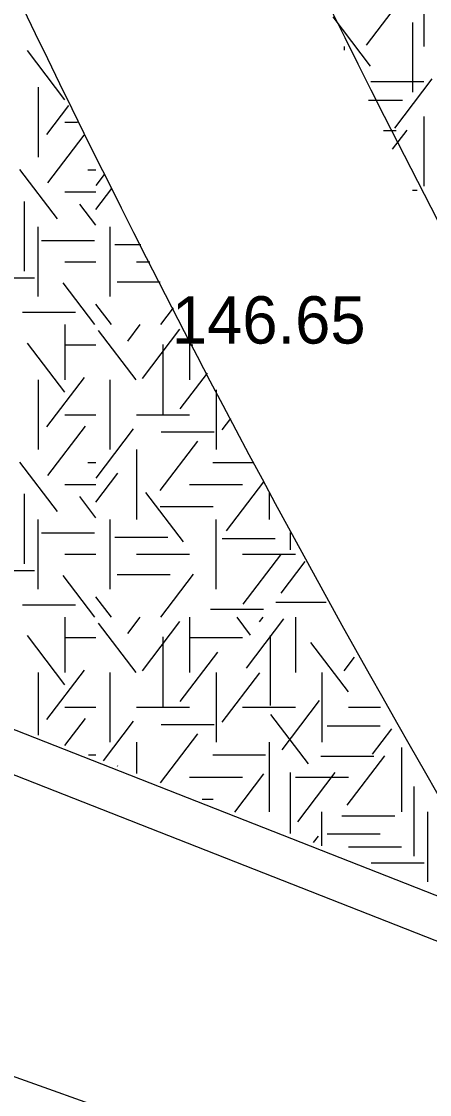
# Model space of a CAD drawing. Extents: x 419677 to 421689, y 4450851 to 4452923.
# Drawn here: x 420247.89 to 420258.24, y 4452050.44 to 4452077.62 of the extents above; entities that cross this region are included whole.
import ezdxf

# ---------------------------------------------------------------- set-up
doc = ezdxf.new("R2010")
doc.units = 0
for name, color, linetype in [('AA_HH', 7, 'Continuous'), ('Level 41', 7, 'Continuous'), ('Level 62', 7, 'Continuous')]:
    doc.layers.add(name, color=color, linetype=linetype)

msp = doc.modelspace()

# ---------------------------------------------------------------- linework, layer by layer
at = {"layer": 'Level 41'}
for p, q in [((420256.636, 4452077.019), (420257.585, 4452078.269)), ((420258.089, 4452078.382), (420258.089, 4452076.984)), ((420256.743, 4452076.493), (420255.794, 4452077.742)), ((420257.807, 4452077.594), (420257.807, 4452075.827)), ((420248.989, 4452075.638), (420248.04, 4452076.887)), ((420256.075, 4452076.984), (420256.075, 4452076.899)), ((420256.746, 4452076.1), (420258.089, 4452076.1)), ((420257.356, 4452074.916), (420258.305, 4452076.166)), ((420248.317, 4452075.954), (420248.317, 4452074.187)), ((420248.317, 4452075.954), (420248.317, 4452074.187)), ((420248.537, 4452074.761), (420249.091, 4452075.491)), ((420256.693, 4452075.63), (420257.549, 4452075.63)), ((420258.089, 4452075.217), (420258.089, 4452073.45)), ((420248.988, 4452075.07), (420249.309, 4452075.07)), ((420248.563, 4452073.535), (420249.48, 4452074.741)), ((420257.068, 4452074.86), (420257.389, 4452074.86)), ((420257.299, 4452074.386), (420257.666, 4452074.869)), ((420248.802, 4452072.623), (420247.853, 4452073.872)), ((420249.572, 4452073.863), (420249.776, 4452073.863)), ((420249.786, 4452073.466), (420249.997, 4452073.744)), ((420248.988, 4452073.303), (420249.776, 4452073.303)), ((420249.776, 4452072.857), (420250.181, 4452073.39)), ((420257.803, 4452073.352), (420257.923, 4452073.352)), ((420247.963, 4452073.065), (420247.963, 4452071.297)), ((420249.776, 4452072.463), (420249.37, 4452072.997)), ((420248.317, 4452070.652), (420248.317, 4452072.42)), ((420250.138, 4452070.652), (420250.138, 4452072.42)), ((420248.399, 4452072.077), (420249.742, 4452072.077)), ((420250.261, 4452071.971), (420250.917, 4452071.971)), ((420248.988, 4452071.536), (420249.776, 4452071.536)), ((420250.809, 4452071.536), (420251.142, 4452071.536)), ((420246.881, 4452071.129), (420248.224, 4452071.129)), ((420249.747, 4452069.943), (420248.945, 4452070.999)), ((420250.315, 4452071.025), (420251.407, 4452071.025)), ((420250.17, 4452069.943), (420249.776, 4452070.461)), ((420251.423, 4452069.943), (420251.747, 4452070.37)), ((420247.92, 4452070.255), (420249.263, 4452070.255)), ((420248.988, 4452069.943), (420248.988, 4452068.545)), ((420248.988, 4452069.943), (420248.988, 4452068.545)), ((420250.797, 4452068.545), (420249.848, 4452069.795)), ((420250.586, 4452069.526), (420250.903, 4452069.943)), ((420250.957, 4452068.58), (420251.906, 4452069.83)), ((420252.152, 4452069.589), (420252.152, 4452068.545)), ((420248.989, 4452068.229), (420248.04, 4452069.478)), ((420248.988, 4452069.429), (420249.776, 4452069.429)), ((420251.477, 4452069.441), (420251.477, 4452067.674)), ((420252.152, 4452069.429), (420252.235, 4452069.429)), ((420251.917, 4452067.808), (420252.606, 4452068.715)), ((420248.317, 4452068.545), (420248.317, 4452066.778)), ((420248.317, 4452068.545), (420248.317, 4452066.778)), ((420248.537, 4452067.352), (420249.486, 4452068.602)), ((420250.138, 4452066.778), (420250.138, 4452068.545)), ((420252.824, 4452068.294), (420252.824, 4452066.778)), ((420248.988, 4452067.661), (420249.776, 4452067.661)), ((420250.809, 4452067.661), (420252.152, 4452067.661)), ((420248.563, 4452066.126), (420249.513, 4452067.375)), ((420252.983, 4452067.283), (420253.2, 4452067.569)), ((420249.786, 4452066.057), (420250.735, 4452067.306)), ((420251.433, 4452067.227), (420252.776, 4452067.227)), ((420250.809, 4452066.778), (420250.809, 4452065.011)), ((420251.411, 4452065.74), (420252.36, 4452066.99)), ((420248.802, 4452065.214), (420247.853, 4452066.463)), ((420249.572, 4452066.454), (420249.776, 4452066.454)), ((420252.739, 4452066.454), (420253.778, 4452066.454)), ((420249.776, 4452065.448), (420250.335, 4452066.184)), ((420253.088, 4452064.724), (420254.032, 4452065.966)), ((420248.988, 4452065.894), (420249.776, 4452065.894)), ((420251.996, 4452064.443), (420251.047, 4452065.693)), ((420252.152, 4452065.894), (420253.495, 4452065.894)), ((420254.167, 4452065.705), (420254.167, 4452065.011)), ((420247.963, 4452065.656), (420247.963, 4452063.888)), ((420249.776, 4452065.054), (420249.37, 4452065.588)), ((420251.406, 4452065.334), (420252.749, 4452065.334)), ((420248.317, 4452063.243), (420248.317, 4452065.011)), ((420250.138, 4452063.243), (420250.138, 4452065.011)), ((420252.824, 4452063.243), (420252.824, 4452065.011)), ((420248.399, 4452064.668), (420249.742, 4452064.668)), ((420254.699, 4452064.679), (420254.699, 4452064.238)), ((420250.261, 4452064.562), (420251.604, 4452064.562)), ((420252.978, 4452064.528), (420254.321, 4452064.528)), ((420248.988, 4452064.127), (420249.776, 4452064.127)), ((420250.809, 4452064.127), (420252.152, 4452064.127)), ((420253.495, 4452064.127), (420254.838, 4452064.127)), ((420253.514, 4452062.867), (420254.463, 4452064.116)), ((420254.474, 4452063.146), (420255.08, 4452063.944)), ((420246.881, 4452063.72), (420248.224, 4452063.72)), ((420249.747, 4452062.534), (420248.945, 4452063.59)), ((420250.315, 4452063.616), (420251.657, 4452063.616)), ((420251.423, 4452062.534), (420252.252, 4452063.625)), ((420250.17, 4452062.534), (420249.776, 4452063.052)), ((420247.92, 4452062.846), (420249.263, 4452062.846)), ((420252.685, 4452062.74), (420254.028, 4452062.74)), ((420254.337, 4452062.915), (420255.614, 4452062.915)), ((420248.988, 4452062.534), (420248.988, 4452061.136)), ((420248.988, 4452062.534), (420248.988, 4452061.136)), ((420250.586, 4452062.117), (420250.903, 4452062.534)), ((420250.957, 4452061.171), (420251.906, 4452062.421)), ((420252.152, 4452062.534), (420252.152, 4452061.136)), ((420253.701, 4452062.082), (420253.357, 4452062.534)), ((420253.594, 4452061.24), (420254.544, 4452062.49)), ((420253.927, 4452062.414), (420254.018, 4452062.534)), ((420254.838, 4452062.534), (420254.838, 4452061.136)), ((420250.797, 4452061.136), (420249.848, 4452062.386)), ((420248.989, 4452060.82), (420248.04, 4452062.069)), ((420248.988, 4452062.02), (420249.776, 4452062.02)), ((420251.477, 4452062.032), (420251.477, 4452060.265)), ((420252.152, 4452062.02), (420253.495, 4452062.02)), ((420254.194, 4452062.067), (420254.194, 4452060.3)), ((420256.178, 4452060.645), (420255.229, 4452061.894)), ((420251.917, 4452060.399), (420252.866, 4452061.649)), ((420256.071, 4452061.171), (420256.337, 4452061.521)), ((420248.317, 4452061.136), (420248.317, 4452059.542)), ((420248.317, 4452061.136), (420248.317, 4452059.542)), ((420248.537, 4452059.943), (420249.486, 4452061.193)), ((420250.138, 4452059.369), (420250.138, 4452061.136)), ((420252.824, 4452061.136), (420252.824, 4452059.369)), ((420252.983, 4452059.874), (420253.932, 4452061.124)), ((420255.51, 4452061.136), (420255.51, 4452059.369)), ((420248.988, 4452060.252), (420249.776, 4452060.252)), ((420250.809, 4452060.252), (420252.152, 4452060.252)), ((420253.495, 4452060.252), (420254.838, 4452060.252)), ((420254.5, 4452059.173), (420255.451, 4452060.422)), ((420256.181, 4452060.252), (420256.996, 4452060.252)), ((420255.166, 4452058.823), (420254.216, 4452060.072)), ((420248.991, 4452059.28), (420249.513, 4452059.966)), ((420249.975, 4452058.897), (420250.735, 4452059.897)), ((420251.433, 4452059.818), (420252.776, 4452059.818)), ((420255.641, 4452059.782), (420256.984, 4452059.782)), ((420256.791, 4452059.068), (420257.277, 4452059.709)), ((420251.414, 4452058.336), (420252.36, 4452059.581)), ((420250.809, 4452059.369), (420250.809, 4452058.572)), ((420254.167, 4452059.369), (420254.167, 4452057.602)), ((420257.524, 4452059.233), (420257.524, 4452057.602)), ((420249.594, 4452059.045), (420249.776, 4452059.045)), ((420252.739, 4452059.045), (420254.082, 4452059.045)), ((420255.481, 4452059.012), (420256.824, 4452059.012)), ((420256.151, 4452057.771), (420257.101, 4452059.021)), ((420250.324, 4452058.76), (420250.335, 4452058.775)), ((420252.152, 4452058.485), (420253.495, 4452058.485)), ((420253.304, 4452057.599), (420254.038, 4452058.565)), ((420254.699, 4452058.597), (420254.699, 4452057.056)), ((420254.838, 4452058.485), (420256.181, 4452058.485)), ((420254.899, 4452057.351), (420255.848, 4452058.6)), ((420257.842, 4452058.247), (420257.842, 4452056.479)), ((420252.468, 4452057.925), (420252.749, 4452057.925)), ((420255.51, 4452056.74), (420255.51, 4452057.602)), ((420258.196, 4452055.834), (420258.196, 4452057.602)), ((420256.015, 4452057.504), (420257.358, 4452057.504)), ((420255.298, 4452056.823), (420255.423, 4452056.987)), ((420255.641, 4452057.048), (420256.984, 4452057.048)), ((420256.181, 4452056.718), (420257.524, 4452056.718)), ((420256.76, 4452056.311), (420258.103, 4452056.311))]:
    msp.add_line(p, q, dxfattribs=at)
at = {"layer": 'Level 62'}
for p, q in [((420260.753, 4452054.556), (420228.234, 4452067.324)), ((420261.321, 4452053.19), (420236.91, 4452062.774)), ((420253.468, 4452048.845), (420235.027, 4452055.395))]:
    msp.add_line(p, q, dxfattribs=at)
for radius, start, end in [(283.529, 191.1934, 210.35878), (290.529, 193.40687, 211.16796), (275.029, 202.37988, 213.0871)]:
    msp.add_arc((420509.913, 4452203.553), radius, start, end, dxfattribs=at)

# ---------------------------------------------------------------- texts
at = {"layer": 'AA_HH'}
msp.add_text('146.65 ', height=1.2, rotation=0.0026, dxfattribs=at).set_placement((420251.706, 4452069.463))

doc.saveas('drawing.dxf')
